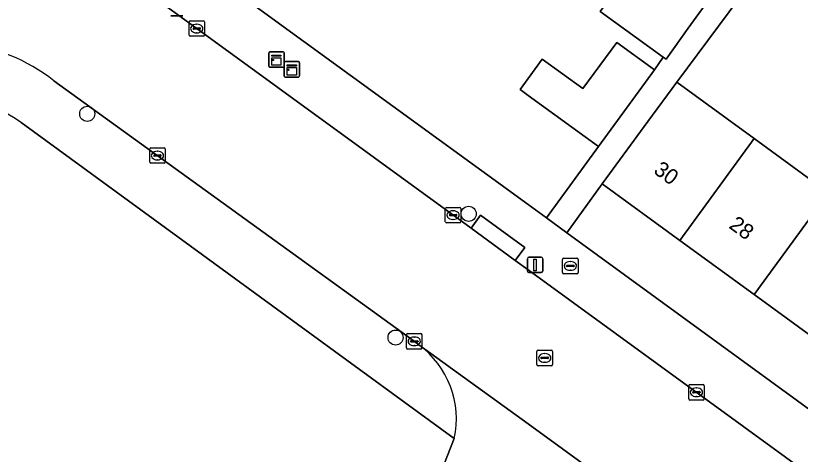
# Model space of a CAD drawing. Extents: x 159674 to 160531, y 382172 to 382904.
# Drawn here: x 159966.8 to 160017.6, y 382378.6 to 382407 of the extents above; entities that cross this region are included whole.
import ezdxf

# ---------------------------------------------------------------- set-up
doc = ezdxf.new("R2010")
doc.units = 0
for name, color, linetype in [('IMGEO_Boom', 7, 'Continuous'), ('IMGEO_Brandkraan', 7, 'Continuous'), ('IMGEO_Erf', 7, 'Continuous'), ('IMGEO_Groenvoorziening', 7, 'Continuous'), ('IMGEO_Kast', 7, 'Continuous'), ('IMGEO_Kolk', 7, 'Continuous'), ('IMGEO_Lichtmast', 7, 'Continuous'), ('IMGEO_Pand', 7, 'Continuous'), ('IMGEO_Pand_nummerreeks', 7, 'Continuous'), ('IMGEO_Rijbaan_lokaal_gesloten', 7, 'Continuous'), ('IMGEO_Rijbaan_lokaal_open', 7, 'Continuous'), ('IMGEO_Rioolput', 7, 'Continuous'), ('IMGEO_Voetpad_open', 7, 'Continuous')]:
    doc.layers.add(name, color=color, linetype=linetype)

msp = doc.modelspace()

# ---------------------------------------------------------------- linework, layer by layer
at = {"layer": 'IMGEO_Boom'}
for centre in [(159971.473, 382400.653), (159996.156, 382394.176), (159991.427, 382386.161)]:
    msp.add_circle(centre, 0.489, dxfattribs=at)
at = {"layer": 'IMGEO_Brandkraan'}
for p, q in [((160002.235, 382390.373), (160002.235, 382391.225)), ((160002.31, 382391.299), (160003.162, 382391.299)), ((160003.236, 382391.225), (160003.236, 382390.373)), ((160002.494, 382390.793), (160002.494, 382390.805)), ((160002.932, 382390.756), (160002.534, 382390.756)), ((160002.537, 382390.842), (160002.935, 382390.842)), ((160002.723, 382391.079), (160002.748, 382391.079)), ((160002.978, 382390.805), (160002.978, 382390.793)), ((160003.162, 382390.299), (160002.31, 382390.299)), ((160002.746, 382390.519), (160002.721, 382390.519))]:
    msp.add_line(p, q, dxfattribs=at)
for points in [[(160002.235, 382390.373), (160002.235, 382391.225)], [(160002.31, 382391.299), (160003.162, 382391.299)], [(160003.236, 382391.225), (160003.236, 382390.373)], [(160003.162, 382390.299), (160002.31, 382390.299)]]:
    msp.add_lwpolyline(points, dxfattribs=at)
for centre, radius, start, end in [((160002.312, 382391.223), 0.0765, 91.552, 178.448), ((160002.312, 382391.223), 0.0765, 91.552, 178.448), ((160003.16, 382391.223), 0.0765, 1.552, 88.448), ((160003.16, 382391.223), 0.0765, 1.552, 88.448), ((160002.534, 382390.802), 0.0403, 85.8775, 175.7526), ((160002.531, 382390.792), 0.0366, 178.938, 274.7102), ((160002.935, 382390.799), 0.043, 264.8664, 352.4533), ((160002.939, 382390.804), 0.0386, 1.7309, 96.639), ((160002.312, 382390.375), 0.0765, 181.552, 268.448), ((160002.312, 382390.375), 0.0765, 181.552, 268.448), ((160003.16, 382390.375), 0.0765, 271.552, 358.448), ((160003.16, 382390.375), 0.0765, 271.552, 358.448)]:
    msp.add_arc(centre, radius, start, end, dxfattribs=at)
for centre, major_axis, ratio, start_param, end_param in [((160002.722, 382390.799), (-0.387, 0.002), 0.722429, 4.712389, 7.853982), ((160002.747, 382390.799), (-0.39, 0.002), 0.717154, 1.570796, 4.712389)]:
    msp.add_ellipse(centre, major_axis=major_axis, ratio=ratio, start_param=start_param, end_param=end_param, dxfattribs=at)
at = {"layer": 'IMGEO_Erf'}
for points in [[(159979.733, 382409.536), (160000, 382394.771), (160001.186, 382393.907), (160004.555, 382398.53), (160000, 382401.849), (159999.482, 382402.226), (160000, 382402.937), (160000.92, 382404.2), (160003.553, 382402.281), (160005.738, 382405.28), (160008.178, 382403.501), (160008.748, 382404.326), (160004.664, 382407.285), (160005.25, 382408.095), (160004.279, 382408.799), (160006.758, 382412.221), (160011.718, 382408.628), (160013.471, 382411.167), (160013.633, 382411.383), (160008.803, 382415.005), (160010.178, 382416.839), (160011.675, 382418.835), (160016.505, 382415.212), (160020.603, 382421.017)], [(160017.707, 382413.601), (160009.634, 382402.696), (160014.631, 382399.046), (160019.438, 382395.527)]]:
    msp.add_lwpolyline(points, dxfattribs=at)
msp.add_lwpolyline([(160029.188, 382378.345), (160024.432, 382381.81), (160019.577, 382385.347), (160014.641, 382388.943), (160009.826, 382392.451), (160004.805, 382396.109), (160002.502, 382392.948), (160051.264, 382357.423), (160053.567, 382360.584), (160048.682, 382364.143), (160043.927, 382367.607), (160038.909, 382371.263), (160034.141, 382374.737)], close=True, dxfattribs=at)
at = {"layer": 'IMGEO_Groenvoorziening'}
msp.add_lwpolyline([(159992.155, 382374.522), (159994.35, 382377.434), (159995.228, 382379.629), (159967.191, 382400.081)], dxfattribs=at)
msp.add_arc((159961.779, 382392.708), 9.146, 53.7219, 113.0455, dxfattribs=at)
at = {"layer": 'IMGEO_Kast'}
for p, q in [((159983.216, 382403.746), (159983.216, 382404.587)), ((159983.216, 382404.587), (159983.216, 382403.746)), ((159983.291, 382404.671), (159984.132, 382404.671)), ((159984.132, 382404.671), (159983.291, 382404.671)), ((159984.216, 382404.596), (159984.216, 382403.755)), ((159984.216, 382403.755), (159984.216, 382404.596)), ((159984.218, 382403.107), (159984.218, 382403.948)), ((159984.218, 382403.948), (159984.218, 382403.107)), ((159984.293, 382404.032), (159985.134, 382404.032)), ((159985.134, 382404.032), (159984.293, 382404.032)), ((159985.218, 382403.957), (159985.218, 382403.116)), ((159985.218, 382403.116), (159985.218, 382403.957)), ((159984.141, 382403.671), (159983.3, 382403.671)), ((159983.3, 382403.671), (159984.141, 382403.671)), ((159985.143, 382403.032), (159984.302, 382403.032)), ((159984.302, 382403.032), (159985.143, 382403.032))]:
    msp.add_line(p, q, dxfattribs=at)
for points in [[(159983.411, 382404.461), (159984.011, 382404.461), (159984.011, 382404.376), (159983.411, 382404.376), (159983.411, 382404.461)], [(159983.411, 382404.286), (159984.011, 382404.286), (159984.011, 382403.797), (159983.411, 382403.797), (159983.411, 382404.286)], [(159984.413, 382403.822), (159985.013, 382403.822), (159985.013, 382403.737), (159984.413, 382403.737), (159984.413, 382403.822)], [(159984.413, 382403.647), (159985.013, 382403.647), (159985.013, 382403.158), (159984.413, 382403.158), (159984.413, 382403.647)]]:
    msp.add_lwpolyline(points, dxfattribs=at)
for centre in [(159983.495, 382404.135), (159984.497, 382403.496)]:
    msp.add_circle(centre, 0.0377, dxfattribs=at)
for centre, start, end in [((159983.294, 382404.593), 92.4484, 184.2845), ((159983.294, 382404.593), 92.4484, 184.2845), ((159984.138, 382404.593), 2.4484, 94.2845), ((159984.138, 382404.593), 2.4484, 94.2845), ((159984.296, 382403.954), 92.4484, 184.2845), ((159984.296, 382403.954), 92.4484, 184.2845), ((159985.14, 382403.954), 2.4484, 94.2845), ((159985.14, 382403.954), 2.4484, 94.2845), ((159983.294, 382403.749), 182.4484, 274.2845), ((159983.294, 382403.749), 182.4484, 274.2845), ((159984.138, 382403.749), 272.4484, 4.2845), ((159984.138, 382403.749), 272.4484, 4.2845), ((159984.296, 382403.11), 182.4484, 274.2845), ((159984.296, 382403.11), 182.4484, 274.2845), ((159985.14, 382403.11), 272.4484, 4.2845), ((159985.14, 382403.11), 272.4484, 4.2845)]:
    msp.add_arc(centre, 0.0779, start, end, dxfattribs=at)
at = {"layer": 'IMGEO_Kolk'}
for p, q in [((159978.062, 382405.747), (159978.062, 382406.599)), ((159978.137, 382406.673), (159978.989, 382406.673)), ((159978.55, 382406.453), (159978.575, 382406.453)), ((159979.063, 382406.599), (159979.063, 382405.747)), ((159978.321, 382406.167), (159978.321, 382406.179)), ((159978.759, 382406.13), (159978.361, 382406.13)), ((159978.364, 382406.216), (159978.762, 382406.216)), ((159978.573, 382405.893), (159978.548, 382405.893)), ((159978.805, 382406.179), (159978.805, 382406.167)), ((159978.989, 382405.673), (159978.137, 382405.673)), ((159975.516, 382397.524), (159975.516, 382398.376)), ((159975.591, 382398.45), (159976.443, 382398.45)), ((159976.517, 382398.376), (159976.517, 382397.524)), ((159975.775, 382397.944), (159975.775, 382397.956)), ((159976.213, 382397.907), (159975.815, 382397.907)), ((159975.818, 382397.993), (159976.216, 382397.993)), ((159976.004, 382398.23), (159976.029, 382398.23)), ((159976.259, 382397.956), (159976.259, 382397.944)), ((159976.443, 382397.45), (159975.591, 382397.45)), ((159976.027, 382397.67), (159976.002, 382397.67)), ((159994.646, 382393.665), (159994.646, 382394.517)), ((159994.721, 382394.591), (159995.573, 382394.591)), ((159995.134, 382394.371), (159995.159, 382394.371)), ((159995.647, 382394.517), (159995.647, 382393.665)), ((159994.905, 382394.085), (159994.905, 382394.097)), ((159995.343, 382394.048), (159994.945, 382394.048)), ((159994.948, 382394.134), (159995.346, 382394.134)), ((159995.157, 382393.811), (159995.132, 382393.811)), ((159995.389, 382394.097), (159995.389, 382394.085)), ((159995.573, 382393.591), (159994.721, 382393.591)), ((159992.135, 382385.492), (159992.135, 382386.344)), ((159992.21, 382386.418), (159993.062, 382386.418)), ((159992.623, 382386.198), (159992.648, 382386.198)), ((159993.136, 382386.344), (159993.136, 382385.492)), ((159992.394, 382385.912), (159992.394, 382385.924)), ((159992.832, 382385.875), (159992.434, 382385.875)), ((159992.437, 382385.961), (159992.835, 382385.961)), ((159992.646, 382385.638), (159992.621, 382385.638)), ((159992.878, 382385.924), (159992.878, 382385.912)), ((159993.062, 382385.418), (159992.21, 382385.418)), ((160010.397, 382382.192), (160010.397, 382383.044)), ((160010.472, 382383.118), (160011.324, 382383.118)), ((160011.398, 382383.044), (160011.398, 382382.192)), ((160010.656, 382382.612), (160010.656, 382382.624)), ((160011.094, 382382.575), (160010.696, 382382.575)), ((160010.699, 382382.661), (160011.097, 382382.661)), ((160010.885, 382382.898), (160010.91, 382382.898)), ((160011.14, 382382.624), (160011.14, 382382.612)), ((160011.324, 382382.118), (160010.472, 382382.118)), ((160010.908, 382382.338), (160010.883, 382382.338))]:
    msp.add_line(p, q, dxfattribs=at)
for points in [[(159978.062, 382405.747), (159978.062, 382406.599)], [(159978.137, 382406.673), (159978.989, 382406.673)], [(159979.063, 382406.599), (159979.063, 382405.747)], [(159978.989, 382405.673), (159978.137, 382405.673)], [(159975.516, 382397.524), (159975.516, 382398.376)], [(159975.591, 382398.45), (159976.443, 382398.45)], [(159976.517, 382398.376), (159976.517, 382397.524)], [(159976.443, 382397.45), (159975.591, 382397.45)], [(159994.646, 382393.665), (159994.646, 382394.517)], [(159994.721, 382394.591), (159995.573, 382394.591)], [(159995.647, 382394.517), (159995.647, 382393.665)], [(159995.573, 382393.591), (159994.721, 382393.591)], [(159992.135, 382385.492), (159992.135, 382386.344)], [(159992.21, 382386.418), (159993.062, 382386.418)], [(159993.136, 382386.344), (159993.136, 382385.492)], [(159993.062, 382385.418), (159992.21, 382385.418)], [(160010.397, 382382.192), (160010.397, 382383.044)], [(160010.472, 382383.118), (160011.324, 382383.118)], [(160011.398, 382383.044), (160011.398, 382382.192)], [(160011.324, 382382.118), (160010.472, 382382.118)]]:
    msp.add_lwpolyline(points, dxfattribs=at)
for centre, radius, start, end in [((159978.139, 382406.597), 0.0765, 91.552, 178.448), ((159978.139, 382406.597), 0.0765, 91.552, 178.448), ((159978.987, 382406.597), 0.0765, 1.552, 88.448), ((159978.987, 382406.597), 0.0765, 1.552, 88.448), ((159978.361, 382406.176), 0.0403, 85.8775, 175.7526), ((159978.358, 382406.166), 0.0366, 178.938, 274.7102), ((159978.762, 382406.173), 0.043, 264.8664, 352.4533), ((159978.766, 382406.178), 0.0386, 1.7309, 96.639), ((159978.139, 382405.749), 0.0765, 181.552, 268.448), ((159978.139, 382405.749), 0.0765, 181.552, 268.448), ((159978.987, 382405.749), 0.0765, 271.552, 358.448), ((159978.987, 382405.749), 0.0765, 271.552, 358.448), ((159975.593, 382398.374), 0.0765, 91.552, 178.448), ((159975.593, 382398.374), 0.0765, 91.552, 178.448), ((159976.441, 382398.374), 0.0765, 1.552, 88.448), ((159976.441, 382398.374), 0.0765, 1.552, 88.448), ((159975.815, 382397.953), 0.0403, 85.8775, 175.7526), ((159975.812, 382397.943), 0.0366, 178.938, 274.7102), ((159976.216, 382397.95), 0.043, 264.8664, 352.4533), ((159976.22, 382397.955), 0.0386, 1.7309, 96.639), ((159975.593, 382397.526), 0.0765, 181.552, 268.448), ((159975.593, 382397.526), 0.0765, 181.552, 268.448), ((159976.441, 382397.526), 0.0765, 271.552, 358.448), ((159976.441, 382397.526), 0.0765, 271.552, 358.448), ((159994.723, 382394.515), 0.0765, 91.552, 178.448), ((159994.723, 382394.515), 0.0765, 91.552, 178.448), ((159995.571, 382394.515), 0.0765, 1.552, 88.448), ((159995.571, 382394.515), 0.0765, 1.552, 88.448), ((159994.945, 382394.094), 0.0403, 85.8775, 175.7526), ((159994.942, 382394.084), 0.0366, 178.938, 274.7102), ((159995.346, 382394.091), 0.043, 264.8664, 352.4533), ((159995.35, 382394.096), 0.0386, 1.7309, 96.639), ((159994.723, 382393.667), 0.0765, 181.552, 268.448), ((159994.723, 382393.667), 0.0765, 181.552, 268.448), ((159995.571, 382393.667), 0.0765, 271.552, 358.448), ((159995.571, 382393.667), 0.0765, 271.552, 358.448), ((159992.212, 382386.342), 0.0765, 91.552, 178.448), ((159992.212, 382386.342), 0.0765, 91.552, 178.448), ((159993.06, 382386.342), 0.0765, 1.552, 88.448), ((159993.06, 382386.342), 0.0765, 1.552, 88.448), ((159992.434, 382385.921), 0.0403, 85.8775, 175.7526), ((159992.431, 382385.911), 0.0366, 178.938, 274.7102), ((159992.835, 382385.918), 0.043, 264.8664, 352.4533), ((159992.839, 382385.923), 0.0386, 1.7309, 96.639), ((159992.212, 382385.494), 0.0765, 181.552, 268.448), ((159992.212, 382385.494), 0.0765, 181.552, 268.448), ((159993.06, 382385.494), 0.0765, 271.552, 358.448), ((159993.06, 382385.494), 0.0765, 271.552, 358.448), ((160010.474, 382383.042), 0.0765, 91.552, 178.448), ((160010.474, 382383.042), 0.0765, 91.552, 178.448), ((160011.322, 382383.042), 0.0765, 1.552, 88.448), ((160011.322, 382383.042), 0.0765, 1.552, 88.448), ((160010.696, 382382.621), 0.0403, 85.8775, 175.7526), ((160010.693, 382382.611), 0.0366, 178.938, 274.7102), ((160011.097, 382382.618), 0.043, 264.8664, 352.4533), ((160011.101, 382382.623), 0.0386, 1.7309, 96.639), ((160010.474, 382382.194), 0.0765, 181.552, 268.448), ((160010.474, 382382.194), 0.0765, 181.552, 268.448), ((160011.322, 382382.194), 0.0765, 271.552, 358.448), ((160011.322, 382382.194), 0.0765, 271.552, 358.448)]:
    msp.add_arc(centre, radius, start, end, dxfattribs=at)
for centre, major_axis, ratio, start_param, end_param in [((159978.549, 382406.173), (-0.387, 0.002), 0.722429, 4.712389, 7.853982), ((159978.574, 382406.173), (-0.39, 0.002), 0.717154, 1.570796, 4.712389), ((159976.003, 382397.95), (-0.387, 0.002), 0.722429, 4.712389, 7.853982), ((159976.028, 382397.95), (-0.39, 0.002), 0.717154, 1.570796, 4.712389), ((159995.133, 382394.091), (-0.387, 0.002), 0.722429, 4.712389, 7.853982), ((159995.158, 382394.091), (-0.39, 0.002), 0.717154, 1.570796, 4.712389), ((159992.622, 382385.918), (-0.387, 0.002), 0.722429, 4.712389, 7.853982), ((159992.647, 382385.918), (-0.39, 0.002), 0.717154, 1.570796, 4.712389), ((160010.884, 382382.618), (-0.387, 0.002), 0.722429, 4.712389, 7.853982), ((160010.909, 382382.618), (-0.39, 0.002), 0.717154, 1.570796, 4.712389)]:
    msp.add_ellipse(centre, major_axis=major_axis, ratio=ratio, start_param=start_param, end_param=end_param, dxfattribs=at)
at = {"layer": 'IMGEO_Lichtmast'}
for p, q in [((159977.663, 382407.007), (159976.873, 382407.007)), ((159976.873, 382407.007), (159977.663, 382407.007)), ((159999.959, 382390.467), (159999.959, 382391.267)), ((159999.959, 382391.267), (159999.959, 382390.467)), ((160000.059, 382391.367), (160000.849, 382391.367)), ((160000.849, 382391.367), (160000.059, 382391.367)), ((160000.949, 382391.267), (160000.949, 382390.467)), ((160000.949, 382390.467), (160000.949, 382391.267)), ((160000.849, 382390.367), (160000.059, 382390.367)), ((160000.059, 382390.367), (160000.849, 382390.367))]:
    msp.add_line(p, q, dxfattribs=at)
msp.add_lwpolyline([(160000.379, 382391.242), (160000.529, 382391.242), (160000.529, 382390.492), (160000.379, 382390.492), (160000.379, 382391.242)], dxfattribs=at)
for centre, start, end in [((160000.059, 382391.267), 90, 180), ((160000.059, 382391.267), 90, 180), ((160000.849, 382391.267), 0, 90), ((160000.849, 382391.267), 360, 90), ((160000.059, 382390.467), 180, 270), ((160000.059, 382390.467), 180, 270), ((160000.849, 382390.467), 270, 0), ((160000.849, 382390.467), 270, 0)]:
    msp.add_arc(centre, 0.1, start, end, dxfattribs=at)
at = {"layer": 'IMGEO_Pand'}
for points in [[(160006.758, 382412.221), (160004.279, 382408.799), (160005.25, 382408.095), (160004.664, 382407.285), (160008.748, 382404.326), (160008.928, 382404.196), (160010.355, 382406.208), (160011.973, 382408.444), (160011.718, 382408.628)], [(160004.555, 382398.53), (160008.178, 382403.501), (160005.738, 382405.28), (160003.553, 382402.281), (160000.92, 382404.2), (160000, 382402.937), (159999.482, 382402.226), (160000, 382401.849)], [(160014.631, 382399.046), (160009.634, 382402.696), (160007.75, 382400.151), (160004.805, 382396.109), (160009.826, 382392.451)], [(160019.438, 382395.527), (160014.631, 382399.046), (160009.826, 382392.451), (160014.641, 382388.943)], [(160024.375, 382391.93), (160019.438, 382395.527), (160014.641, 382388.943), (160019.577, 382385.347)]]:
    msp.add_lwpolyline(points, close=True, dxfattribs=at)
at = {"layer": 'IMGEO_Rijbaan_lokaal_gesloten'}
for points in [[(160000, 382390.554), (159999.175, 382391.156), (159996.317, 382393.238), (159977.556, 382406.905), (159976.539, 382407.646), (159971.594, 382411.249), (159957.027, 382404.415)], [(159969.32, 382402.798), (159992.637, 382385.919), (159992.936, 382385.697), (160000, 382380.567), (160006.662, 382375.729), (160031.337, 382357.71), (160031.812, 382357.364), (160045.029, 382347.737), (160045.468, 382347.417), (160070.304, 382329.392), (160079.622, 382322.53)], [(160078.11, 382333.649), (160000, 382390.554)]]:
    msp.add_lwpolyline(points, dxfattribs=at)
msp.add_arc((159961.781, 382393.016), 12.35, 52.3754, 112.6374, dxfattribs=at)
at = {"layer": 'IMGEO_Rijbaan_lokaal_open'}
for points in [[(160006.662, 382375.729), (160000, 382380.567), (159992.936, 382385.697)], [(159995.228, 382379.629), (159994.35, 382377.434), (159992.155, 382374.522)]]:
    msp.add_lwpolyline(points, dxfattribs=at)
msp.add_arc((159989.368, 382380.883), 5.992, 347.9248, 53.4602, dxfattribs=at)
at = {"layer": 'IMGEO_Rioolput'}
for p, q in [((160000.577, 382384.416), (160000.577, 382385.268)), ((160000.652, 382385.342), (160001.504, 382385.342)), ((160001.065, 382385.122), (160001.09, 382385.122)), ((160001.578, 382385.268), (160001.578, 382384.416)), ((160000.836, 382384.836), (160000.836, 382384.848)), ((160001.274, 382384.799), (160000.876, 382384.799)), ((160000.879, 382384.885), (160001.277, 382384.885)), ((160001.088, 382384.562), (160001.063, 382384.562)), ((160001.32, 382384.848), (160001.32, 382384.836)), ((160001.504, 382384.342), (160000.652, 382384.342))]:
    msp.add_line(p, q, dxfattribs=at)
for points in [[(160000.577, 382384.416), (160000.577, 382385.268)], [(160000.652, 382385.342), (160001.504, 382385.342)], [(160001.578, 382385.268), (160001.578, 382384.416)], [(160001.504, 382384.342), (160000.652, 382384.342)]]:
    msp.add_lwpolyline(points, dxfattribs=at)
for centre, radius, start, end in [((160000.654, 382385.266), 0.0765, 91.552, 178.448), ((160000.654, 382385.266), 0.0765, 91.552, 178.448), ((160001.502, 382385.266), 0.0765, 1.552, 88.448), ((160001.502, 382385.266), 0.0765, 1.552, 88.448), ((160000.876, 382384.845), 0.0403, 85.8775, 175.7526), ((160000.873, 382384.835), 0.0366, 178.938, 274.7102), ((160001.277, 382384.842), 0.043, 264.8664, 352.4533), ((160001.281, 382384.847), 0.0386, 1.7309, 96.639), ((160000.654, 382384.418), 0.0765, 181.552, 268.448), ((160000.654, 382384.418), 0.0765, 181.552, 268.448), ((160001.502, 382384.418), 0.0765, 271.552, 358.448), ((160001.502, 382384.418), 0.0765, 271.552, 358.448)]:
    msp.add_arc(centre, radius, start, end, dxfattribs=at)
for centre, major_axis, ratio, start_param, end_param in [((160001.064, 382384.842), (-0.387, 0.002), 0.722429, 4.712389, 7.853982), ((160001.089, 382384.842), (-0.39, 0.002), 0.717154, 1.570796, 4.712389)]:
    msp.add_ellipse(centre, major_axis=major_axis, ratio=ratio, start_param=start_param, end_param=end_param, dxfattribs=at)
at = {"layer": 'IMGEO_Voetpad_open'}
for points in [[(160020.603, 382421.017), (160016.505, 382415.212), (160016.661, 382415.095), (160015.163, 382413.099), (160013.788, 382411.266), (160013.633, 382411.383), (160013.471, 382411.167), (160011.718, 382408.628), (160011.973, 382408.444), (160010.355, 382406.208), (160008.928, 382404.196), (160008.748, 382404.326), (160008.178, 382403.501), (160004.555, 382398.53), (160001.186, 382393.907), (160002.502, 382392.948), (160004.805, 382396.109), (160007.75, 382400.151), (160009.634, 382402.696), (160017.707, 382413.601)], [(159979.132, 382410.544), (159976.539, 382407.646), (159977.556, 382406.905), (159996.317, 382393.238), (159996.929, 382394.079), (159999.787, 382391.997), (159999.175, 382391.156), (160000, 382390.554), (160078.11, 382333.649)], [(160002.502, 382392.948), (160001.186, 382393.907), (160000, 382394.771), (159979.733, 382409.536)], [(159992.936, 382385.697), (159992.637, 382385.919), (159969.32, 382402.798)], [(159967.191, 382400.081), (159995.228, 382379.629)], [(160076.39, 382339.118), (160053.693, 382355.653), (160051.264, 382357.423), (160002.502, 382392.948)]]:
    msp.add_lwpolyline(points, dxfattribs=at)
msp.add_lwpolyline([(159999.175, 382391.156), (159999.787, 382391.997), (159996.929, 382394.079), (159996.317, 382393.238)], close=True, dxfattribs=at)
for centre, radius, start, end in [((159961.781, 382393.016), 12.35, 52.3754, 112.6374), ((159961.779, 382392.708), 9.146, 53.7219, 113.0455), ((159989.368, 382380.883), 5.992, 347.9248, 53.4602)]:
    msp.add_arc(centre, radius, start, end, dxfattribs=at)

# ---------------------------------------------------------------- texts
at = {"layer": 'IMGEO_Pand_nummerreeks'}
for s, p in [('30', (160008.061, 382396.855)), ('28', (160012.937, 382393.302))]:
    msp.add_text(s, height=1, rotation=323.9266, dxfattribs=at).set_placement(p)

doc.saveas('drawing.dxf')
